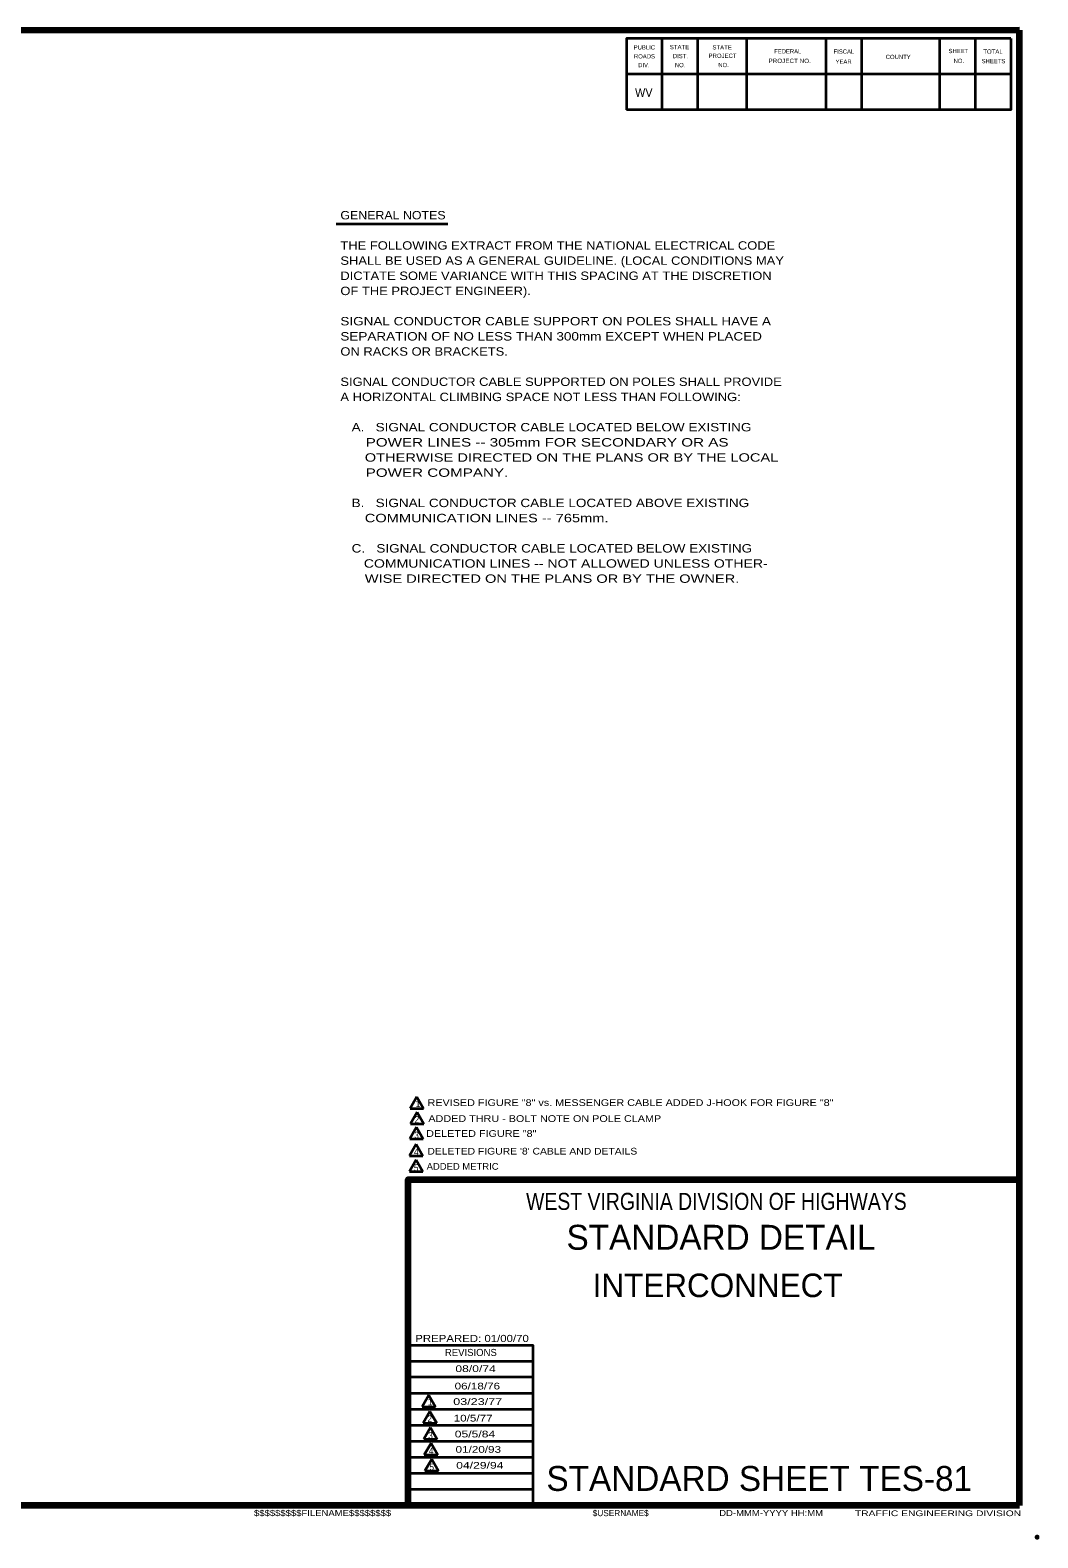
# Model space of a CAD drawing. Extents: x -421 to 434, y -46 to 498.
# Drawn here: x 75 to 434, y -46 to 492 of the extents above; entities that cross this region are included whole.
import ezdxf
from ezdxf.enums import TextEntityAlignment as Align

# ---------------------------------------------------------------- set-up
doc = ezdxf.new("R2010")
doc.units = 0
doc.header["$LTSCALE"] = 0.96
doc.header["$PDMODE"] = 32
doc.header["$PDSIZE"] = 0.48
doc.layers.add('1', color=7, linetype='Continuous', lineweight=53)
doc.layers.add('61', color=7, linetype='Continuous', lineweight=35)

msp = doc.modelspace()

# ---------------------------------------------------------------- linework, layer by layer
at = {"layer": '1', "lineweight": 158}
for q in [(427.565, 491.8976), (427.565, 82.0976), (-364.035, -34.2024)]:
    msp.add_line((427.565, -34.2024), q, dxfattribs=at)
at = {"layer": '1', "lineweight": 13}
msp.add_line((427.565, -34.2024), (427.565, 491.8976), dxfattribs=at)
at = {"layer": '1', "lineweight": 35}
for p, q in [((183.919, 422.8022), (223.6936, 422.8022)), ((212.6391, 111.4879), (210.2391, 107.331)), ((212.6391, 111.4879), (215.0391, 107.331)), ((210.2391, 107.331), (215.0391, 107.331)), ((212.7453, 106.071), (210.3453, 101.9141)), ((212.7453, 106.071), (215.1453, 101.9141)), ((212.533, 100.6539), (210.133, 96.497)), ((210.3453, 101.9141), (215.1453, 101.9141)), ((212.533, 100.6539), (214.933, 96.497)), ((212.3898, 94.6374), (209.9898, 90.4805)), ((210.133, 96.497), (214.933, 96.497)), ((212.3898, 94.6374), (214.7898, 90.4805)), ((212.3897, 88.9971), (209.9897, 84.8402)), ((209.9898, 90.4805), (214.7898, 90.4805)), ((212.3897, 88.9971), (214.7897, 84.8402)), ((209.9897, 84.8402), (214.7897, 84.8402)), ((254.065, 17.1976), (209.565, 17.1976)), ((254.065, 11.4976), (209.565, 11.4976)), ((254.065, 5.6976), (209.565, 5.6976)), ((216.9457, 5.1772), (214.5457, 1.0203)), ((214.5457, 1.0203), (219.3457, 1.0203)), ((216.9457, 5.1772), (219.3457, 1.0203)), ((254.065, -0.0024), (209.565, -0.0024)), ((217.3132, -0.6318), (214.9132, -4.7887)), ((214.9132, -4.7887), (219.7132, -4.7887)), ((217.3132, -0.6318), (219.7132, -4.7887)), ((254.065, -5.7024), (209.565, -5.7024)), ((217.4929, -6.441), (215.0929, -10.5979)), ((215.0929, -10.5979), (219.8929, -10.5979)), ((217.4929, -6.441), (219.8929, -10.5979)), ((254.065, -11.4024), (209.565, -11.4024)), ((217.7004, -11.9661), (215.3004, -16.123)), ((215.3004, -16.123), (220.1004, -16.123)), ((217.7004, -11.9661), (220.1004, -16.123)), ((254.065, -17.1024), (209.565, -17.1024)), ((217.9283, -17.7369), (215.5283, -21.8938)), ((217.9283, -17.7369), (220.3283, -21.8938)), ((254.065, -22.8024), (209.565, -22.8024)), ((215.5283, -21.8938), (220.3283, -21.8938)), ((254.065, -28.5024), (209.565, -28.5024))]:
    msp.add_line(p, q, dxfattribs=at)
at = {"layer": '1', "lineweight": 158}
for points in [[(427.565, 491.8976), (-364.135, 491.7976), (-364.035, -34.2024)], [(209.565, -34.2024), (209.565, 82.0976), (427.565, 82.0976)]]:
    msp.add_lwpolyline(points, dxfattribs=at)
at = {"layer": '1', "lineweight": 35}
msp.add_lwpolyline([(254.065, -34.2024), (254.065, 22.8976), (209.565, 22.8976)], dxfattribs=at)
at = {"layer": '1'}
msp.add_point((433.865, -45.5024), dxfattribs=at)
at = {"layer": '61'}
for p, q in [((300.065, 488.8976), (300.065, 463.4976)), ((312.765, 488.8976), (312.765, 463.4976)), ((330.165, 488.8976), (330.165, 463.4976)), ((358.465, 488.8976), (358.465, 463.4976)), ((371.165, 488.8976), (371.165, 463.4976)), ((399.065, 488.8976), (399.065, 463.4976)), ((411.765, 488.8976), (411.765, 463.4976)), ((424.465, 476.1976), (287.365, 476.1976))]:
    msp.add_line(p, q, dxfattribs=at)
at = {"layer": '61', "lineweight": 53}
for q in [(274.865, -34.2024), (274.865, -34.2024), (274.865, -34.2024), (275.165, -34.2024), (275.165, -34.2024)]:
    msp.add_line((427.565, -34.2024), q, dxfattribs=at)
at = {"layer": '61'}
for points in [[(424.465, 488.8976), (287.365, 488.8976), (287.365, 463.4976)], [(424.465, 488.8976), (424.465, 463.4976), (287.365, 463.4976)]]:
    msp.add_lwpolyline(points, dxfattribs=at)

# ---------------------------------------------------------------- texts
at = {"layer": '1'}
for s, height, width, p in [('WV', 3.048, 0.95, (290.465, 468.0976)), ('GENERAL NOTES', 3, 1.1, (185.3711, 424.4166)), ('THE FOLLOWING EXTRACT FROM THE NATIONAL ELECTRICAL CODE', 3, 1.15, (185.3711, 413.6166)), ('SHALL BE USED AS A GENERAL GUIDELINE. (LOCAL CONDITIONS MAY', 3, 1.15, (185.3711, 408.2166)), ('DICTATE SOME VARIANCE WITH THIS SPACING AT THE DISCRETION', 3, 1.15, (185.3711, 402.8166)), ('OF THE PROJECT ENGINEER).', 3, 1.15, (185.3711, 397.4166)), ('SIGNAL CONDUCTOR CABLE SUPPORT ON POLES SHALL HAVE A', 3, 1.2, (185.3711, 386.6166)), ('SEPARATION OF NO LESS THAN 300mm EXCEPT WHEN PLACED', 3, 1.2, (185.3711, 381.2166)), ('ON RACKS OR BRACKETS.', 3, 1.15, (185.3711, 375.8166)), ('SIGNAL CONDUCTOR CABLE SUPPORTED ON POLES SHALL PROVIDE', 3, 1.15, (185.3711, 365.0166)), ('A HORIZONTAL CLIMBING SPACE NOT LESS THAN FOLLOWING:', 3, 1.15, (185.3711, 359.6166)), ('   A.   SIGNAL CONDUCTOR CABLE LOCATED BELOW EXISTING', 3, 1.2, (185.3711, 348.8166)), ('      POWER LINES -- 305mm FOR SECONDARY OR AS', 3, 1.35, (185.3711, 343.4166)), ('      OTHERWISE DIRECTED ON THE PLANS OR BY THE LOCAL', 3, 1.3, (185.3711, 338.0166)), ('      POWER COMPANY.', 3, 1.35, (185.3711, 332.6166)), ('   B.   SIGNAL CONDUCTOR CABLE LOCATED ABOVE EXISTING', 3, 1.2, (185.3711, 321.8166)), ('      COMMUNICATION LINES -- 765mm.', 3, 1.3, (185.3711, 316.4166)), ('   C.   SIGNAL CONDUCTOR CABLE LOCATED BELOW EXISTING', 3, 1.2, (185.3711, 305.6166)), ('      COMMUNICATION LINES -- NOT ALLOWED UNLESS OTHER-', 3, 1.25, (185.3711, 300.2166)), ('      WISE DIRECTED ON THE PLANS OR BY THE OWNER.', 3, 1.3, (185.3711, 294.8166)), ('2', 2.397, 0.9, (211.8488, 102.2243)), ('3', 2.397, 0.9, (211.7427, 96.7012)), ('4', 2.397, 0.95, (211.5995, 90.6847)), ('5', 2.397, 0.9, (211.5994, 85.0444)), ('PREPARED: 01/00/70', 2.537, 1.2, (212.065, 24.0976)), ('08/0/74', 2.397, 1.35, (226.3733, 13.3734)), ('06/18/76', 2.397, 1.3, (226.1037, 7.1722)), ('03/23/77', 2.397, 1.4, (225.6055, 1.6493)), ('2', 2.397, 0.9, (216.4167, -4.4785)), ('10/5/77', 2.397, 1.3, (225.7606, -4.2661)), ('3', 2.397, 0.9, (216.7026, -10.3937)), ('05/5/84', 2.397, 1.35, (226.1526, -9.9315)), ('4', 2.397, 0.95, (216.9101, -15.9188)), ('01/20/93', 2.397, 1.3, (226.4472, -15.4076)), ('5', 2.397, 0.9, (217.138, -21.6896)), ('04/29/94', 2.397, 1.35, (226.6752, -21.0813)), ('$$$$$$$$$FILENAME$$$$$$$$', 2.2, 1.15, (154.565, -38.0024)), ('DD-MMM-YYYY HH:MM', 2.2, 1.15, (320.465, -38.0024)), ('TRAFFIC ENGINEERING DIVISION', 2.031, 1.35, (368.865, -38.0024))]:
    msp.add_text(s, height=height, dxfattribs=dict(at, width=width)).set_placement(p)
for s, height, p in [('1', 2.397, (212.1674, 107.8537)), ('REVISIONS', 2.537, (222.665, 19.0976)), ('1', 2.397, (216.474, 1.543)), ('STANDARD SHEET TES-81', 8.881, (258.865, -29.0024)), ('$USERNAME$', 2.2, (275.365, -38.0024))]:
    msp.add_text(s, height=height, dxfattribs=at).set_placement(p)
for s, height, width, p in [('REVISED FIGURE "8" vs. MESSENGER CABLE ADDED J-HOOK FOR FIGURE "8"', 2.4, 1.2, (288.8362, 108.2621)), ('ADDED THRU - BOLT NOTE ON POLE CLAMP', 2.4, 1.2, (258.2586, 102.5714)), ('DELETED FIGURE "8"', 2.4, 1.2, (235.6221, 97.2364)), ("DELETED FIGURE '8' CABLE AND DETAILS", 2.4, 1.15, (253.8092, 90.9334)), ('ADDED METRIC', 2.4, 1.05, (228.9644, 85.5112)), ('WEST VIRGINIA DIVISION OF HIGHWAYS', 6.089, 0.85, (319.465, 71.1976))]:
    msp.add_text(s, height=height, dxfattribs=dict(at, width=width)).set_placement(p, align=Align.CENTER)
for s, height, p in [('STANDARD DETAIL', 8.881, (321.115, 56.9976)), ('INTERCONNECT', 8.391, (319.9001, 40.0988))]:
    msp.add_text(s, height=height, dxfattribs=at).set_placement(p, align=Align.CENTER)
at = {"layer": '61'}
for s, height, rotation, p in [('PUBLIC', 1.525, 0.033, (289.965, 484.9976)), ('FEDERAL', 1.523, 0.007, (340.065, 483.5976)), ('FISCAL', 1.525, 359.942, (361.265, 483.4976)), ('SHEET', 1.525, 0.059, (402.265, 483.6976)), ('ROADS', 1.525, 0.124, (290.065, 481.7976)), ('DIV.', 1.525, 359.932, (291.565, 478.6976)), ('DIST.', 1.525, 0.056, (303.965, 481.8976)), ('YEAR', 1.523, 0.105, (361.965, 479.8976)), ('COUNTY', 1.523, 0.069, (379.865, 481.5976)), ('SHEETS', 1.523, 359.959, (414.065, 480.0976))]:
    msp.add_text(s, height=height, rotation=rotation, dxfattribs=at).set_placement(p)
for s, rotation, width, p in [('STATE', 0.059, 1.05, (302.865, 485.0976)), ('STATE', 0.059, 1.05, (318.065, 484.9976)), ('TOTAL', 359.926, 1.05, (414.665, 483.4976)), ('NO.', 359.852, 0.9, (304.665, 478.6976)), ('PROJECT', 359.908, 1.05, (316.665, 481.9976)), ('NO.', 0.225, 0.9, (320.165, 478.6976)), ('PROJECT NO.', 359.922, 1.1, (338.065, 480.1976)), ('NO.', 359.852, 0.9, (404.065, 480.1976))]:
    msp.add_text(s, height=1.525, rotation=rotation, dxfattribs=dict(at, width=width)).set_placement(p)

doc.saveas('drawing.dxf')
